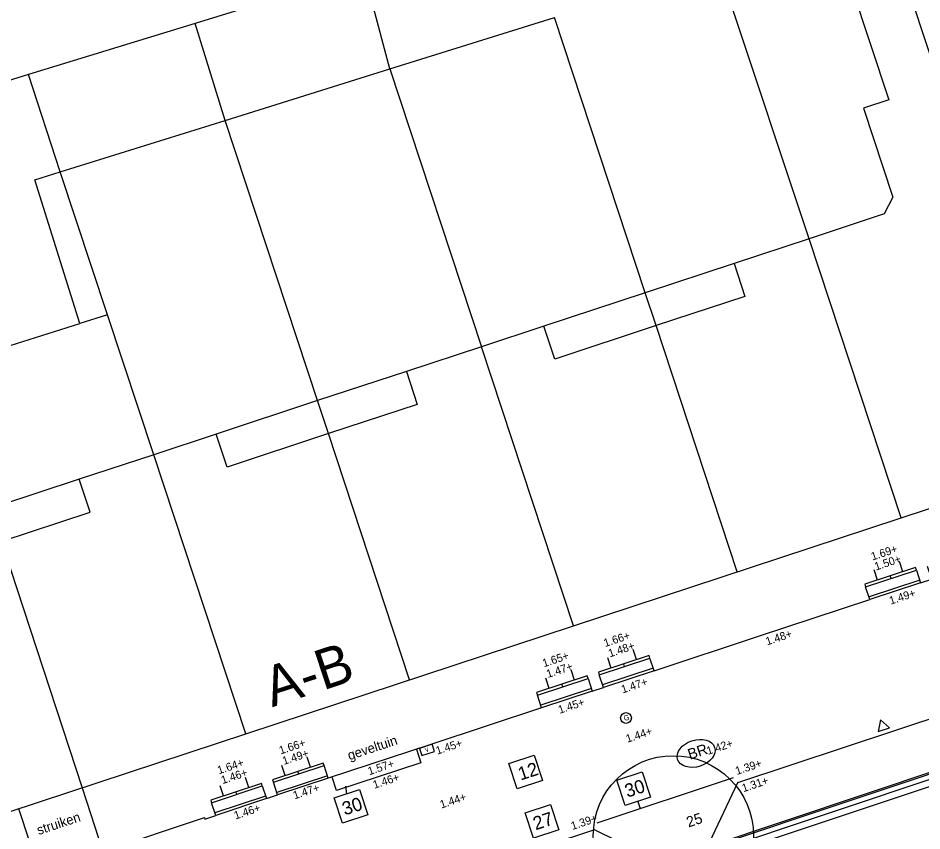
# Model space of a CAD drawing. Extents: x 122462 to 123306, y 485548 to 486417.
# Drawn here: x 122724.72 to 122758.59, y 486167.98 to 486198.43 of the extents above; entities that cross this region are included whole.
import ezdxf

# ---------------------------------------------------------------- set-up
doc = ezdxf.new("R2010")
doc.units = 0
for name, color, linetype in [('B meubilair trammast', 7, 'Continuous'), ('B-WE-AL-T25', 7, 'Continuous'), ('B-WE-AL-WERKGRENS-G', 7, 'Continuous'), ('B-WE-GR-BOOM_BOOMDIAMETER', 7, 'Continuous'), ('B-WE-IE-MEUBILAIR_WEGMEUBILAIR_VERKEERSBORD-S', 7, 'Continuous'), ('B-WE-KL-DATA_TELECOM_KAST-S', 7, 'Continuous'), ('B-WE-OG-BEBOUWING_PORTIEK1-G', 7, 'Continuous'), ('B-WE-OG-BEBOUWING_TRAP-G', 7, 'Continuous'), ('B-WE-OG-HOOGTEPUNT-S', 7, 'Continuous'), ('B-WE-OG-TOPOKAART-G', 7, 'Continuous'), ('B-WE-VH-KANTOPSLUITING_OPSLUITBAND_100X200-G', 7, 'Continuous'), ('iba7-verkeersbord blauw', 7, 'Continuous'), ('iba7-verkeersbord rood', 7, 'Continuous'), ('Level 1', 7, 'Continuous'), ('Level 19', 7, 'Continuous'), ('Level 4', 7, 'Continuous'), ('N-WE-AL-T25', 7, 'Continuous'), ('V markering 1-1 10 cm', 7, 'Continuous'), ('V markering ononderbroken streep 10 cm', 7, 'Continuous'), ('V materiaalscheiding algemeen', 7, 'Continuous'), ('V opsluitband 100x200 mm', 7, 'Continuous'), ('V trottoirband 180-200x250 mm specie', 7, 'Continuous'), ('X-WE-AL-TEKENBLAD-S', 7, 'Continuous')]:
    doc.layers.add(name, color=color, linetype=linetype)

msp = doc.modelspace()

# ---------------------------------------------------------------- linework, layer by layer
at = {"layer": 'B meubilair trammast'}
msp.add_lwpolyline([(122756.949, 486171.709), (122757.377, 486171.849), (122757.042, 486172.149)], close=True, dxfattribs=at)
at = {"layer": 'B-WE-AL-WERKGRENS-G'}
msp.add_lwpolyline([(122857.632, 486078.279), (122830.484, 486160.606), (122900.937, 486183.81), (122887.855, 486222.555), (122665.445, 486149.273), (122678.196, 486110.449), (122807.072, 486152.895), (122835.324, 486068.154)], dxfattribs=at)
at = {"layer": 'B-WE-KL-DATA_TELECOM_KAST-S'}
msp.add_lwpolyline([(122740.243, 486171.228), (122739.768, 486171.072), (122739.856, 486170.806), (122740.33, 486170.962)], close=True, dxfattribs=at)
at = {"layer": 'B-WE-OG-BEBOUWING_PORTIEK1-G'}
for p, q in [((122757.876, 486177.693), (122757.751, 486178.073)), ((122756.927, 486177.38), (122756.801, 486177.76)), ((122757.433, 486177.442), (122757.402, 486177.537)), ((122747.892, 486174.399), (122747.766, 486174.779)), ((122746.942, 486174.086), (122746.817, 486174.465)), ((122747.448, 486174.147), (122747.417, 486174.242)), ((122745.574, 486173.634), (122745.448, 486174.014)), ((122744.624, 486173.321), (122744.499, 486173.701)), ((122745.13, 486173.382), (122745.099, 486173.477)), ((122735.686, 486170.371), (122735.561, 486170.751)), ((122734.737, 486170.058), (122734.611, 486170.437)), ((122735.243, 486170.119), (122735.212, 486170.214)), ((122733.369, 486169.606), (122733.243, 486169.986)), ((122732.419, 486169.293), (122732.294, 486169.673)), ((122732.925, 486169.354), (122732.894, 486169.449))]:
    msp.add_line(p, q, dxfattribs=at)
for points in [[(122756.483, 486177.128), (122758.382, 486177.755), (122758.351, 486177.85), (122756.452, 486177.223)], [(122746.498, 486173.834), (122748.398, 486174.461), (122748.366, 486174.556), (122746.467, 486173.929)], [(122744.181, 486173.069), (122746.08, 486173.696), (122746.049, 486173.791), (122744.149, 486173.164)], [(122734.293, 486169.806), (122736.193, 486170.433), (122736.161, 486170.528), (122734.262, 486169.901)], [(122731.975, 486169.041), (122733.875, 486169.668), (122733.843, 486169.763), (122731.944, 486169.136)]]:
    msp.add_lwpolyline(points, close=True, dxfattribs=at)
at = {"layer": 'B-WE-OG-BEBOUWING_TRAP-G'}
for points in [[(122758.508, 486177.375), (122756.609, 486176.749)], [(122758.539, 486177.28), (122756.64, 486176.654)], [(122748.523, 486174.081), (122746.624, 486173.454)], [(122748.554, 486173.986), (122746.655, 486173.359)], [(122746.205, 486173.316), (122744.306, 486172.689)], [(122746.237, 486173.221), (122744.337, 486172.594)], [(122736.318, 486170.053), (122734.419, 486169.426)], [(122736.349, 486169.958), (122734.45, 486169.331)], [(122734, 486169.288), (122732.101, 486168.661)], [(122734.031, 486169.193), (122732.132, 486168.566)]]:
    msp.add_lwpolyline(points, dxfattribs=at)
at = {"layer": 'B-WE-OG-TOPOKAART-G'}
for p, q in [((122756.64, 486176.654), (122756.483, 486177.128)), ((122748.554, 486173.986), (122748.398, 486174.461)), ((122744.337, 486172.594), (122744.181, 486173.069)), ((122736.349, 486169.958), (122736.193, 486170.433)), ((122732.132, 486168.565), (122731.975, 486169.041))]:
    msp.add_line(p, q, dxfattribs=at)
for points in [[(122758.382, 486177.755), (122758.539, 486177.28), (122758.958, 486177.418), (122758.801, 486177.893)], [(122748.554, 486173.986), (122752.465, 486175.276), (122756.64, 486176.654)], [(122746.08, 486173.696), (122746.237, 486173.221), (122746.655, 486173.359), (122746.498, 486173.834)], [(122744.337, 486172.594), (122740.191, 486171.226), (122736.349, 486169.958)], [(122733.875, 486169.668), (122734.031, 486169.193), (122734.45, 486169.331), (122734.293, 486169.806)], [(122727.121, 486169.595), (122727.9, 486167.219), (122731.704, 486168.482), (122731.719, 486168.429), (122732.132, 486168.565)]]:
    msp.add_lwpolyline(points, dxfattribs=at)
at = {"layer": 'B-WE-VH-KANTOPSLUITING_OPSLUITBAND_100X200-G'}
msp.add_lwpolyline([(122727.9, 486167.219), (122725.535, 486166.433), (122724.753, 486168.814)], dxfattribs=at)
at = {"layer": 'iba7-verkeersbord blauw'}
msp.add_circle((122747.503, 486172.214), 0.2, dxfattribs=at)
msp.add_ellipse((122750.129, 486170.888), major_axis=(-0.693, -0.227), ratio=0.685994, dxfattribs=at)
at = {"layer": 'iba7-verkeersbord rood'}
msp.add_circle((122749.278, 486167.803), 3, dxfattribs=at)
at = {"layer": 'Level 1'}
for p, q in [((122760.501, 486192.189), (122757.165, 486202.305)), ((122737.689, 486200.198), (122731.364, 486198.223)), ((122731.364, 486198.223), (122725.118, 486196.312)), ((122738.65, 486196.524), (122744.822, 486198.451)), ((122732.479, 486194.597), (122738.65, 486196.524)), ((122725.118, 486196.312), (122719.85, 486194.699)), ((122726.307, 486192.67), (122732.479, 486194.597)), ((122754.363, 486190.167), (122751.55, 486189.24)), ((122751.55, 486189.24), (122748.225, 486188.145)), ((122748.225, 486188.145), (122744.426, 486186.893)), ((122722.685, 486185.626), (122727.035, 486186.985)), ((122744.426, 486186.893), (122742.087, 486186.122)), ((122742.087, 486186.122), (122739.274, 486185.195)), ((122739.274, 486185.195), (122735.949, 486184.1)), ((122735.949, 486184.1), (122732.15, 486182.848)), ((122732.15, 486182.848), (122729.811, 486182.077)), ((122729.811, 486182.077), (122727.016, 486181.156)), ((122727.016, 486181.156), (122723.689, 486180.059)), ((122723.689, 486180.059), (122727.121, 486169.595))]:
    msp.add_line(p, q, dxfattribs=at)
for points in [[(122751.331, 486199.294), (122753.241, 486199.89), (122752.903, 486200.974), (122755.256, 486201.709), (122757.349, 486195.363), (122756.4, 486195.05), (122757.497, 486191.726), (122757.179, 486191.095), (122754.363, 486190.167)], [(122727.035, 486186.985), (122725.353, 486192.372), (122726.307, 486192.67)]]:
    msp.add_lwpolyline(points, dxfattribs=at)
at = {"layer": 'Level 19'}
for p, q in [((122754.363, 486190.167), (122751.331, 486199.294)), ((122748.225, 486188.145), (122744.822, 486198.451)), ((122738.65, 486196.524), (122742.087, 486186.122)), ((122735.949, 486184.1), (122732.479, 486194.597)), ((122728.08, 486187.311), (122726.307, 486192.67)), ((122728.08, 486187.311), (122727.035, 486186.985)), ((122729.811, 486182.077), (122728.08, 486187.311))]:
    msp.add_line(p, q, dxfattribs=at)
at = {"layer": 'Level 4'}
for p, q in [((122738.65, 486196.524), (122737.689, 486200.198)), ((122732.479, 486194.597), (122731.364, 486198.223)), ((122726.307, 486192.67), (122725.118, 486196.312)), ((122757.81, 486179.706), (122754.363, 486190.167)), ((122748.632, 486186.91), (122748.225, 486188.145)), ((122751.672, 486177.684), (122748.632, 486186.91)), ((122745.534, 486175.661), (122742.087, 486186.122)), ((122736.356, 486182.866), (122735.949, 486184.1)), ((122739.396, 486173.639), (122736.356, 486182.866)), ((122733.258, 486171.617), (122729.811, 486182.077))]:
    msp.add_line(p, q, dxfattribs=at)
at = {"layer": 'N-WE-AL-T25'}
for p, q in [((122751.55, 486189.241), (122751.55, 486189.24)), ((122739.274, 486185.196), (122739.274, 486185.195)), ((122732.15, 486182.848), (122732.15, 486182.849))]:
    msp.add_line(p, q, dxfattribs=at)
for points in [[(122751.55, 486189.24), (122751.957, 486188.006), (122748.632, 486186.91)], [(122748.632, 486186.91), (122744.833, 486185.658), (122744.426, 486186.893)], [(122739.274, 486185.195), (122739.681, 486183.961), (122736.356, 486182.866)], [(122736.356, 486182.866), (122732.557, 486181.614), (122732.15, 486182.848)], [(122724.096, 486178.827), (122727.42, 486179.922), (122727.016, 486181.156)]]:
    msp.add_lwpolyline(points, dxfattribs=at)
at = {"layer": 'V markering 1-1 10 cm'}
msp.add_line((122774.598, 486175.14), (122727.918, 486159.59), dxfattribs=at)
msp.add_lwpolyline([(122774.677, 486174.903), (122727.997, 486159.353)], dxfattribs=at)
at = {"layer": 'V markering ononderbroken streep 10 cm'}
msp.add_line((122761.511, 486171.05), (122750.527, 486167.381), dxfattribs=at)
at = {"layer": 'V materiaalscheiding algemeen'}
msp.add_lwpolyline([(122761.53, 486170.993), (122750.546, 486167.324)], dxfattribs=at)
at = {"layer": 'V opsluitband 100x200 mm'}
for points in [[(122739.654, 486171.047), (122739.821, 486170.538), (122736.657, 486169.5), (122736.491, 486170.001)], [(122746.424, 486168.293), (122751.527, 486169.98)]]:
    msp.add_lwpolyline(points, dxfattribs=at)
at = {"layer": 'V trottoirband 180-200x250 mm specie'}
msp.add_lwpolyline([(122772.234, 486176.591), (122764.613, 486174.078), (122763.348, 486171.596), (122761.53, 486170.993), (122760.929, 486172.847), (122759.643, 486172.424), (122751.679, 486169.79), (122750.518, 486167.331), (122748.806, 486166.796), (122746.321, 486168.026), (122738.818, 486165.54)], dxfattribs=at)
at = {"layer": 'X-WE-AL-TEKENBLAD-S'}
for p, q in [((122737.044, 486169.375), (122737.001, 486169.666)), ((122747.944, 486169.092), (122748.033, 486168.825))]:
    msp.add_line(p, q, dxfattribs=at)
for points in [[(122743.11, 486170.51), (122744.06, 486170.824), (122744.373, 486169.874), (122743.423, 486169.561)], [(122747.156, 486169.885), (122748.106, 486170.198), (122748.419, 486169.248), (122747.47, 486168.935)], [(122736.569, 486169.218), (122737.518, 486169.532), (122737.832, 486168.582), (122736.882, 486168.269)], [(122743.719, 486168.663), (122744.669, 486168.977), (122744.982, 486168.027), (122744.033, 486167.714)]]:
    msp.add_lwpolyline(points, close=True, dxfattribs=at)

# ---------------------------------------------------------------- texts
at = {"layer": 'B-WE-AL-T25'}
for s, p in [('geveltuin', (122737.142, 486170.629)), ('struiken', (122725.497, 486167.828))]:
    msp.add_text(s, height=0.36, rotation=18.3134, dxfattribs=at).set_placement(p)
at = {"layer": 'B-WE-GR-BOOM_BOOMDIAMETER'}
msp.add_text('25', height=0.4, rotation=18.301, dxfattribs=at).set_placement((122749.843, 486168.11))
at = {"layer": 'B-WE-IE-MEUBILAIR_WEGMEUBILAIR_VERKEERSBORD-S'}
msp.add_text('A-B', height=1.5, rotation=18.2406, dxfattribs=at).set_placement((122734.242, 486172.612))
at = {"layer": 'B-WE-KL-DATA_TELECOM_KAST-S'}
msp.add_text('V', height=0.16, rotation=18.2705, dxfattribs=at).set_placement((122740, 486170.929))
at = {"layer": 'B-WE-OG-HOOGTEPUNT-S'}
for s, rotation, p in [('1.69+', 18.2611, (122756.738, 486178.112)), ('1.50+', 18.2611, (122756.87, 486177.736)), ('1.49+', 18.2611, (122757.421, 486176.457)), ('1.66+', 18.2611, (122746.72, 486174.869)), ('1.48+', 18.2611, (122752.791, 486174.932)), ('1.48+', 18.2611, (122746.896, 486174.483)), ('1.65+', 18.2611, (122744.427, 486174.113)), ('1.47+', 18.2611, (122744.576, 486173.711)), ('1.47+', 18.2611, (122747.38, 486173.134)), ('1.45+', 18.2611, (122745.017, 486172.371)), ('1.44+', 18.2611, (122747.553, 486171.286)), ('1.66+', 18.2611, (122734.561, 486170.848)), ('1.45+', 18.2611, (122740.431, 486170.837)), ('1.42+', 18.2611, (122750.576, 486170.829)), ('1.49+', 18.2611, (122734.684, 486170.453)), ('1.64+', 18.2611, (122732.249, 486170.103)), ('1.57+', 18.2611, (122737.884, 486170.07)), ('1.39+', 18.4074, (122751.658, 486170.08)), ('1.46+', 18.2611, (122732.386, 486169.736)), ('1.46+', 18.2611, (122738.076, 486169.561)), ('1.31+', 18.4074, (122751.903, 486169.435)), ('1.47+', 18.2611, (122735.084, 486169.164)), ('1.44+', 18.2611, (122740.586, 486168.822)), ('1.46+', 18.2611, (122732.871, 486168.411)), ('1.39+', 18.4074, (122745.495, 486168.018))]:
    msp.add_text(s, height=0.3, rotation=rotation, dxfattribs=at).set_placement(p)
at = {"layer": 'iba7-verkeersbord blauw'}
for s, height, p in [('G', 0.2, (122747.448, 486172.097)), ('BR', 0.4, (122749.894, 486170.65))]:
    msp.add_text(s, height=height, rotation=18.1627, dxfattribs=at).set_placement(p)
at = {"layer": 'X-WE-AL-TEKENBLAD-S'}
for s, p in [('12', (122743.556, 486169.868)), ('30', (122747.555, 486169.226)), ('30', (122736.967, 486168.56)), ('27', (122744.118, 486168.005))]:
    msp.add_text(s, height=0.5, rotation=18.2603, dxfattribs=at).set_placement(p)

doc.saveas('drawing.dxf')
